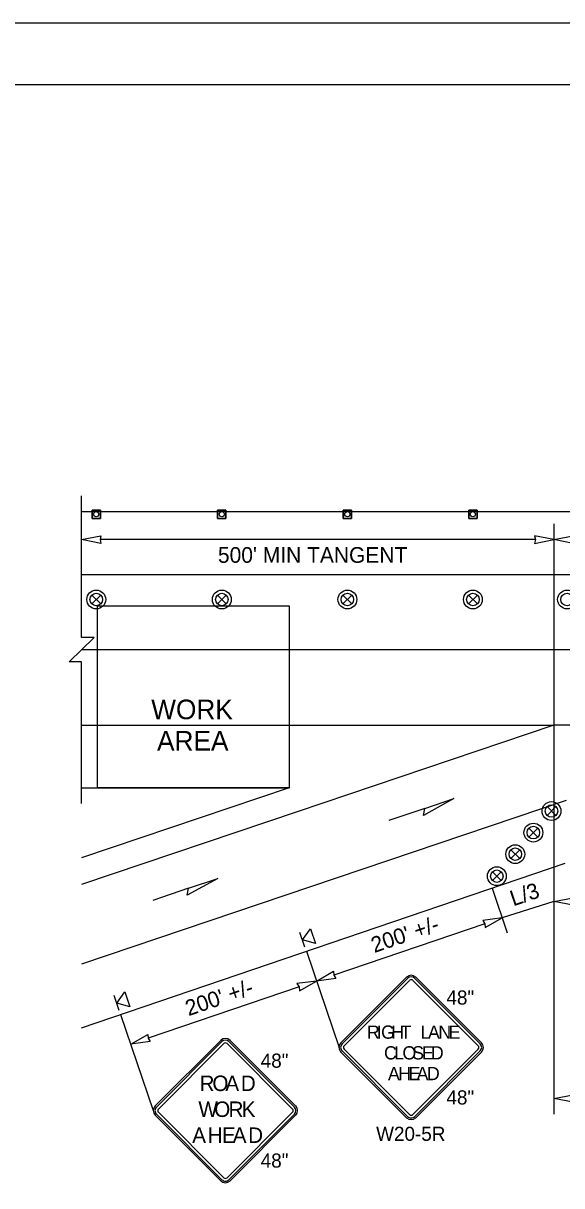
# Model space of a CAD drawing. Extents: x 99999 to 100116, y 99995 to 100013.
# Drawn here: x 100047.9 to 100050.64, y 100004.76 to 100010.69 of the extents above; entities that cross this region are included whole.
import ezdxf

# ---------------------------------------------------------------- set-up
doc = ezdxf.new("R2010")
doc.units = 0
for name, color, linetype in [('RD_MK_LineEdgeYellow', 7, 'Continuous'), ('RD_MK_LineLane', 7, 'Continuous'), ('SH_GI_PlotLimits', 7, 'Continuous'), ('SH_GI_SheetBorder', 7, 'Continuous'), ('TR_SN_ConstructionSigns', 7, 'Continuous'), ('TR_WZ_PortableSignMountBlk-Org', 7, 'Continuous'), ('TR_WZ_TrafficCone', 7, 'Continuous'), ('TR_WZ_TrafficSafetyDrum', 7, 'Continuous'), ('TR_WZ_WorkAreaLabel', 7, 'Continuous'), ('TR_WZ_WorkZoneDetails', 7, 'Continuous'), ('TR_WZ_WorkZoneTextCurrent', 7, 'Continuous')]:
    doc.layers.add(name, color=color, linetype=linetype)

msp = doc.modelspace()

# ---------------------------------------------------------------- linework, layer by layer
at = {"layer": 'RD_MK_LineEdgeYellow'}
for p, q in [((100048.195, 100007.8789), (100055.43, 100007.8789)), ((100048.195, 100007.1109), (100049.2533, 100007.1109)), ((100050.6655, 100006.7269), (100048.195, 100005.8927)), ((100049.2943, 100006.6692), (100048.195, 100006.298))]:
    msp.add_line(p, q, dxfattribs=at)
at = {"layer": 'RD_MK_LineLane'}
for points in [[(100055.43, 100007.4949), (100048.195, 100007.4949)], [(100052.1758, 100007.1109), (100050.6024, 100007.1109)], [(100052.1758, 100007.1109), (100050.6024, 100007.1109)]]:
    msp.add_lwpolyline(points, dxfattribs=at)
at = {"layer": 'SH_GI_PlotLimits'}
msp.add_lwpolyline([(100039.0625, 99999.6875), (100056.0625, 99999.6875), (100056.0625, 100010.6875), (100039.0625, 100010.6875)], close=True, dxfattribs=at)
at = {"layer": 'SH_GI_SheetBorder'}
msp.add_line((100040, 100010.375), (100055.75, 100010.375), dxfattribs=at)
at = {"layer": 'TR_SN_ConstructionSigns'}
for p, q in [((100049.8509, 100005.8261), (100049.5168, 100005.492)), ((100050.2327, 100005.492), (100049.8986, 100005.8261)), ((100049.8568, 100005.8202), (100049.5227, 100005.4861)), ((100049.5327, 100005.4761), (100049.8668, 100005.8102)), ((100049.8827, 100005.8102), (100050.2168, 100005.4761)), ((100050.2267, 100005.4861), (100049.8926, 100005.8202)), ((100048.9041, 100005.5043), (100048.57, 100005.1702)), ((100048.91, 100005.4983), (100048.5759, 100005.1642)), ((100048.5859, 100005.1543), (100048.92, 100005.4884)), ((100048.9359, 100005.4884), (100049.27, 100005.1543)), ((100049.28, 100005.1642), (100048.9458, 100005.4983)), ((100049.2859, 100005.1702), (100048.9518, 100005.5043)), ((100049.5168, 100005.4443), (100049.8509, 100005.1102)), ((100049.5227, 100005.4503), (100049.8568, 100005.1162)), ((100049.8668, 100005.1261), (100049.5327, 100005.4602)), ((100050.2168, 100005.4602), (100049.8827, 100005.1261)), ((100049.8926, 100005.1162), (100050.2267, 100005.4503)), ((100049.8986, 100005.1102), (100050.2327, 100005.4443)), ((100048.57, 100005.1224), (100048.9041, 100004.7883)), ((100048.5759, 100005.1284), (100048.91, 100004.7943)), ((100048.92, 100004.8043), (100048.5859, 100005.1384)), ((100049.27, 100005.1384), (100048.9359, 100004.8043)), ((100048.9458, 100004.7943), (100049.28, 100005.1284)), ((100048.9518, 100004.7883), (100049.2859, 100005.1224))]:
    msp.add_line(p, q, dxfattribs=at)
for centre, radius, start, end in [((100049.8747, 100005.8023), 0.0338, 45, 135), ((100049.8747, 100005.8023), 0.0253, 45, 135), ((100049.8747, 100005.8023), 0.0113, 45, 135), ((100048.9279, 100005.4804), 0.0338, 45, 135), ((100048.9279, 100005.4804), 0.0253, 45, 135), ((100048.9279, 100005.4804), 0.0113, 45, 135), ((100049.5406, 100005.4682), 0.0338, 135, 225.00001), ((100049.5406, 100005.4682), 0.0253, 135, 225.00001), ((100049.5406, 100005.4682), 0.0113, 135, 225.00001), ((100050.2088, 100005.4682), 0.0113, 315.00002, 45), ((100050.2088, 100005.4682), 0.0253, 315.00002, 45), ((100050.2088, 100005.4682), 0.0338, 315.00001, 45.00001), ((100048.5938, 100005.1463), 0.0338, 135, 225.00001), ((100049.2621, 100005.1463), 0.0338, 315.00001, 45.00001), ((100048.5938, 100005.1463), 0.0253, 135, 225.00001), ((100048.5938, 100005.1463), 0.0113, 135, 225.00001), ((100049.2621, 100005.1463), 0.0113, 315.00002, 45), ((100049.2621, 100005.1463), 0.0253, 315.00002, 45), ((100049.8747, 100005.1341), 0.0253, 225.00001, 315.00002), ((100049.8747, 100005.1341), 0.0113, 225.00001, 315.00002), ((100049.8747, 100005.1341), 0.0338, 225.00001, 315.00001), ((100048.9279, 100004.8122), 0.0338, 225.00001, 315.00001), ((100048.9279, 100004.8122), 0.0253, 225.00001, 315.00002), ((100048.9279, 100004.8122), 0.0113, 225.00001, 315.00002)]:
    msp.add_arc(centre, radius, start, end, dxfattribs=at)
at = {"layer": 'TR_WZ_PortableSignMountBlk-Org'}
for p, q in [((100049.3333, 100005.9787), (100049.3076, 100006.0545)), ((100048.3865, 100005.6569), (100048.3608, 100005.7326))]:
    msp.add_line(p, q, dxfattribs=at)
for points in [[(100049.3205, 100006.0165), (100049.362, 100006.0729), (100049.3877, 100005.9972)], [(100048.3737, 100005.6947), (100048.4152, 100005.7511), (100048.4409, 100005.6753)]]:
    msp.add_lwpolyline(points, close=True, dxfattribs=at)
at = {"layer": 'TR_WZ_TrafficCone'}
for points in [[(100048.2481, 100008.2069), (100048.2907, 100008.2069), (100048.2907, 100008.1642), (100048.2481, 100008.1642), (100048.2481, 100008.2069)], [(100048.2481, 100008.1642), (100048.2907, 100008.1642), (100048.2907, 100008.2069), (100048.2481, 100008.2069), (100048.2481, 100008.1642)], [(100048.8881, 100008.2069), (100048.9307, 100008.2069), (100048.9307, 100008.1642), (100048.8881, 100008.1642), (100048.8881, 100008.2069)], [(100048.8881, 100008.1642), (100048.9307, 100008.1642), (100048.9307, 100008.2069), (100048.8881, 100008.2069), (100048.8881, 100008.1642)], [(100049.5281, 100008.2069), (100049.5707, 100008.2069), (100049.5707, 100008.1642), (100049.5281, 100008.1642), (100049.5281, 100008.2069)], [(100049.5281, 100008.1642), (100049.5707, 100008.1642), (100049.5707, 100008.2069), (100049.5281, 100008.2069), (100049.5281, 100008.1642)], [(100050.1681, 100008.2069), (100050.2107, 100008.2069), (100050.2107, 100008.1642), (100050.1681, 100008.1642), (100050.1681, 100008.2069)], [(100050.1681, 100008.1642), (100050.2107, 100008.1642), (100050.2107, 100008.2069), (100050.1681, 100008.2069), (100050.1681, 100008.1642)]]:
    msp.add_lwpolyline(points, dxfattribs=at)
for centre in [(100048.2694, 100008.1856), (100048.9094, 100008.1856), (100049.5494, 100008.1856), (100050.1894, 100008.1856)]:
    msp.add_circle(centre, 0.0133, dxfattribs=at)
at = {"layer": 'TR_WZ_TrafficSafetyDrum'}
for p, q in [((100048.2468, 100007.7735), (100048.292, 100007.7283)), ((100048.292, 100007.7735), (100048.2468, 100007.7283)), ((100048.8868, 100007.7735), (100048.932, 100007.7283)), ((100048.932, 100007.7735), (100048.8868, 100007.7283)), ((100049.5268, 100007.7735), (100049.572, 100007.7283)), ((100049.572, 100007.7735), (100049.5268, 100007.7283)), ((100050.1668, 100007.7735), (100050.212, 100007.7283)), ((100050.212, 100007.7735), (100050.1668, 100007.7283)), ((100050.5673, 100006.6956), (100050.6125, 100006.6503)), ((100050.6125, 100006.6956), (100050.5673, 100006.6503)), ((100050.4751, 100006.5857), (100050.5203, 100006.5404)), ((100050.5203, 100006.5857), (100050.4751, 100006.5404)), ((100050.3829, 100006.4758), (100050.4281, 100006.4306)), ((100050.4281, 100006.4758), (100050.3829, 100006.4306)), ((100050.2886, 100006.3636), (100050.3339, 100006.3183)), ((100050.3339, 100006.3636), (100050.2886, 100006.3183))]:
    msp.add_line(p, q, dxfattribs=at)
for centre, radius in [((100048.2694, 100007.7509), 0.048), ((100048.2694, 100007.7509), 0.048), ((100048.2694, 100007.7509), 0.032), ((100048.9094, 100007.7509), 0.048), ((100048.9094, 100007.7509), 0.048), ((100048.9094, 100007.7509), 0.032), ((100049.5494, 100007.7509), 0.048), ((100049.5494, 100007.7509), 0.048), ((100049.5494, 100007.7509), 0.032), ((100050.1894, 100007.7509), 0.048), ((100050.1894, 100007.7509), 0.048), ((100050.1894, 100007.7509), 0.032), ((100050.6694, 100007.7509), 0.048), ((100050.6694, 100007.7509), 0.048), ((100050.6694, 100007.7509), 0.032), ((100050.5899, 100006.6729), 0.048), ((100050.5899, 100006.6729), 0.048), ((100050.5899, 100006.6729), 0.032), ((100050.4977, 100006.5631), 0.048), ((100050.4977, 100006.5631), 0.048), ((100050.4977, 100006.5631), 0.032), ((100050.4055, 100006.4532), 0.048), ((100050.4055, 100006.4532), 0.048), ((100050.4055, 100006.4532), 0.032), ((100050.3113, 100006.3409), 0.048), ((100050.3113, 100006.3409), 0.048), ((100050.3113, 100006.3409), 0.032)]:
    msp.add_circle(centre, radius, dxfattribs=at)
at = {"layer": 'TR_WZ_WorkZoneDetails'}
for p, q in [((100048.195, 100008.1989), (100055.43, 100008.1989)), ((100050.6024, 100008.1359), (100050.6024, 100005.1282)), ((100050.5087, 100008.0559), (100048.2887, 100008.0559)), ((100049.2533, 100007.1109), (100050.6024, 100007.1109)), ((100050.6024, 100007.1109), (100049.2943, 100006.6692)), ((100048.195, 100006.7909), (100049.2533, 100006.7909)), ((100049.2533, 100006.7909), (100048.195, 100006.4338)), ((100049.9441, 100006.6859), (100049.7613, 100006.6242)), ((100048.195, 100005.5689), (100050.6601, 100006.4069)), ((100048.7404, 100006.2795), (100048.5576, 100006.2178)), ((100050.2871, 100006.2801), (100050.3643, 100006.0529)), ((100050.6024, 100006.2119), (100050.3386, 100006.1286)), ((100050.2498, 100006.0985), (100049.4805, 100005.8369)), ((100049.3403, 100005.9583), (100049.5069, 100005.4682)), ((100049.303, 100005.7766), (100048.5337, 100005.5151)), ((100048.3935, 100005.6364), (100048.5601, 100005.1463))]:
    msp.add_line(p, q, dxfattribs=at)
msp.add_lwpolyline([(100048.195, 100006.7109), (100048.195, 100007.433), (100048.131, 100007.433), (100048.259, 100007.5569), (100048.195, 100007.5569), (100048.195, 100008.2789)], dxfattribs=at)
for points in [[(100048.195, 100008.0559), (100048.2933, 100008.0751), (100048.2887, 100008.0559), (100048.2933, 100008.0366)], [(100050.6024, 100008.0559), (100050.5041, 100008.0751), (100050.5087, 100008.0559), (100050.5041, 100008.0366)], [(100050.6024, 100008.0559), (100050.7007, 100008.0751), (100050.6962, 100008.0559), (100050.7007, 100008.0366)], [(100048.275, 100006.7909), (100048.275, 100007.7189), (100049.2533, 100007.7189), (100049.2533, 100006.7909)], [(100050.093, 100006.7362), (100049.9371, 100006.651), (100049.9441, 100006.6859)], [(100048.8893, 100006.3298), (100048.7333, 100006.2445), (100048.7404, 100006.2795)], [(100050.6024, 100006.2119), (100050.7007, 100006.2312), (100050.6962, 100006.2119), (100050.7007, 100006.1926)], [(100050.3386, 100006.1286), (100050.2393, 100006.1152), (100050.2498, 100006.0985), (100050.2517, 100006.0787)], [(100049.3918, 100005.8068), (100049.4786, 100005.8567), (100049.4805, 100005.8369), (100049.491, 100005.8202)], [(100049.3918, 100005.8068), (100049.2925, 100005.7934), (100049.303, 100005.7766), (100049.3049, 100005.7569)], [(100048.445, 100005.4849), (100048.5318, 100005.5348), (100048.5337, 100005.5151), (100048.5442, 100005.4983)], [(100050.6024, 100005.2082), (100050.7007, 100005.2275), (100050.6962, 100005.2082), (100050.7007, 100005.1889)]]:
    msp.add_lwpolyline(points, close=True, dxfattribs=at)

# ---------------------------------------------------------------- texts
at = {"layer": 'TR_SN_ConstructionSigns'}
for s, height, p in [('48"', 0.072, (100050.0545, 100005.6867)), ('R', 0.0675, (100049.6493, 100005.5125)), ('I', 0.0675, (100049.6986, 100005.5125)), ('G', 0.0675, (100049.7215, 100005.5125)), ('H', 0.0675, (100049.7728, 100005.5125)), ('T', 0.0675, (100049.8201, 100005.5125)), ('L', 0.0675, (100049.922, 100005.5125)), ('A', 0.0675, (100049.9605, 100005.5125)), ('N', 0.0675, (100050.0131, 100005.5125)), ('E', 0.0675, (100050.0658, 100005.5125)), ('C', 0.0675, (100049.7364, 100005.407)), ('L', 0.0675, (100049.7877, 100005.407)), ('O', 0.0675, (100049.8302, 100005.407)), ('S', 0.0675, (100049.8801, 100005.407)), ('E', 0.0675, (100049.9294, 100005.407)), ('D', 0.0675, (100049.9753, 100005.407)), ('48"', 0.072, (100049.1077, 100005.3649)), ('A', 0.0675, (100049.7566, 100005.3015)), ('H', 0.0675, (100049.8093, 100005.3015)), ('E', 0.0675, (100049.8619, 100005.3015)), ('A', 0.0675, (100049.9024, 100005.3015)), ('D', 0.0675, (100049.9551, 100005.3015)), ('R', 0.0788, (100048.796, 100005.2462)), ('O', 0.0788, (100048.8614, 100005.2462)), ('A', 0.0788, (100048.9276, 100005.2462)), ('D', 0.0788, (100049.0063, 100005.2462)), ('48"', 0.072, (100050.0545, 100005.1776)), ('W', 0.0788, (100048.7901, 100005.114)), ('O', 0.0788, (100048.8705, 100005.114)), ('R', 0.0788, (100048.9437, 100005.114)), ('K', 0.0788, (100049.0106, 100005.114)), ('A', 0.0788, (100048.7586, 100004.9818)), ('H', 0.0788, (100048.8374, 100004.9818)), ('E', 0.0788, (100048.9098, 100004.9818)), ('A', 0.0788, (100048.965, 100004.9818)), ('D', 0.0788, (100049.0437, 100004.9818)), ('W20-5R', 0.072, (100049.6961, 100004.9923)), ('48"', 0.072, (100049.1077, 100004.8558))]:
    msp.add_text(s, height=height, rotation=360, dxfattribs=at).set_placement(p)
at = {"layer": 'TR_WZ_WorkAreaLabel'}
for s, p in [('WORK', (100048.5496, 100007.1409)), ('AREA', (100048.5793, 100006.9809))]:
    msp.add_text(s, height=0.1, dxfattribs=at).set_placement(p)
at = {"layer": 'TR_WZ_WorkZoneTextCurrent'}
msp.add_text("500' MIN TANGENT", height=0.08, dxfattribs=at).set_placement((100048.8897, 100007.9379))
for s, p in [('L/3', (100050.3951, 100006.1869)), ("200' +/-", (100049.6866, 100005.9492)), ("200' +/-", (100048.7398, 100005.6274))]:
    msp.add_text(s, height=0.08, rotation=18.77496, dxfattribs=at).set_placement(p)

doc.saveas('drawing.dxf')
